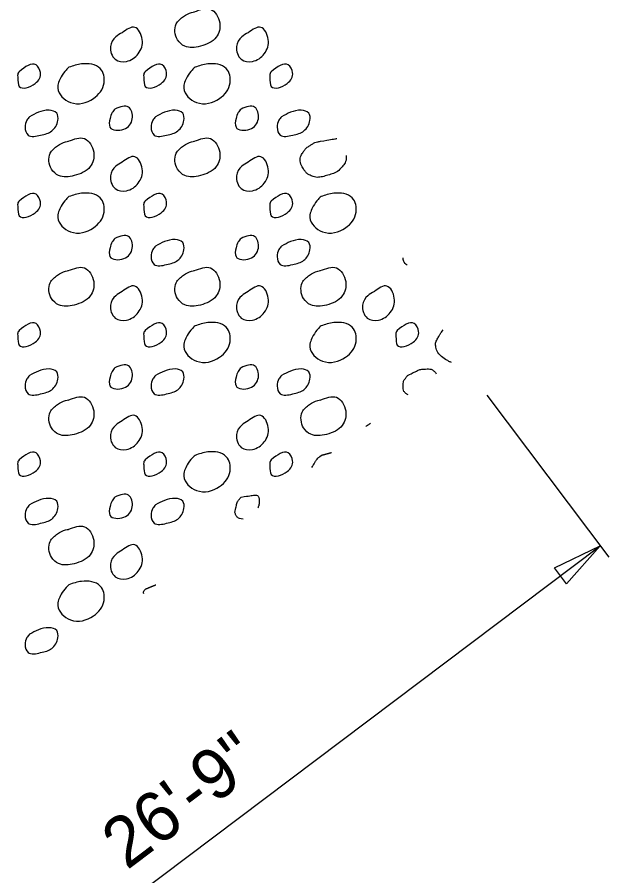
# Model space of a CAD drawing. Extents: x 0 to 1055, y 0 to 220.
# Drawn here: x 232.34 to 248.94, y 118.93 to 143.03 of the extents above; entities that cross this region are included whole.
import ezdxf

# ---------------------------------------------------------------- set-up
doc = ezdxf.new("R2010")
doc.units = 0
doc.layers.add('GE_P_Alignment_100_Distances', color=7, linetype='Continuous')
doc.layers.add('SC_Scratch1', color=7, linetype='Continuous')

msp = doc.modelspace()

# ---------------------------------------------------------------- linework, layer by layer
at = {"layer": 'GE_P_Alignment_100_Distances'}
for p, q in [((245.516, 132.423), (248.939, 127.874)), ((227.354, 112.125), (248.701, 128.19)), ((247.414, 127.572), (248.701, 128.19)), ((248.701, 128.19), (247.751, 127.125)), ((247.751, 127.125), (247.414, 127.572))]:
    msp.add_line(p, q, dxfattribs=at)
at = {"layer": 'SC_Scratch1'}
for points in [[(237.309, 143.177), (237.764, 143.252), (238.023, 142.872), (237.926, 142.466), (237.48, 142.213), (237.04, 142.216), (236.841, 142.394), (236.804, 142.839), (237.009, 143.052), (237.235, 143.161), (237.318, 143.178)], [(235.289, 142.594), (235.641, 142.745), (235.849, 142.407), (235.737, 142.002), (235.404, 141.789), (235.093, 141.848), (234.959, 142.207), (235.105, 142.475), (235.289, 142.594)], [(238.825, 142.594), (239.177, 142.745), (239.384, 142.407), (239.273, 142.002), (238.939, 141.789), (238.629, 141.848), (238.495, 142.207), (238.641, 142.475), (238.825, 142.594)], [(232.395, 141.499), (232.87, 141.692), (232.996, 141.473), (232.847, 141.171), (232.397, 141.087), (232.358, 141.327), (232.362, 141.447), (232.395, 141.499)], [(233.794, 141.625), (234.15, 141.718), (234.671, 141.587), (234.779, 141.184), (234.483, 140.749), (233.834, 140.638), (233.48, 141.037), (233.575, 141.355), (233.714, 141.547), (233.794, 141.625)], [(235.931, 141.499), (236.406, 141.692), (236.532, 141.473), (236.383, 141.171), (235.933, 141.087), (235.894, 141.327), (235.898, 141.447), (235.931, 141.499)], [(237.33, 141.625), (237.686, 141.718), (238.207, 141.587), (238.314, 141.184), (238.019, 140.749), (237.37, 140.638), (237.016, 141.037), (237.111, 141.355), (237.249, 141.547), (237.33, 141.625)], [(239.467, 141.499), (239.942, 141.692), (240.068, 141.473), (239.919, 141.171), (239.469, 141.087), (239.429, 141.327), (239.434, 141.447), (239.467, 141.499)], [(235.085, 140.452), (235.467, 140.508), (235.571, 140.179), (235.331, 139.885), (234.944, 139.942), (234.947, 140.188), (235.005, 140.351), (235.085, 140.452)], [(238.621, 140.452), (239.003, 140.508), (239.107, 140.179), (238.867, 139.885), (238.48, 139.942), (238.483, 140.188), (238.541, 140.351), (238.621, 140.452)], [(232.687, 140.235), (232.937, 140.36), (233.238, 140.418), (233.449, 140.337), (233.483, 140.134), (233.312, 139.837), (232.999, 139.717), (232.647, 139.723), (232.561, 139.939), (232.613, 140.139), (232.687, 140.235)], [(236.223, 140.235), (236.473, 140.36), (236.774, 140.418), (236.984, 140.337), (237.019, 140.134), (236.848, 139.837), (236.534, 139.717), (236.183, 139.723), (236.097, 139.939), (236.149, 140.139), (236.223, 140.235)], [(239.759, 140.235), (240.009, 140.36), (240.309, 140.418), (240.52, 140.337), (240.554, 140.134), (240.384, 139.837), (240.07, 139.717), (239.719, 139.723), (239.633, 139.939), (239.684, 140.139), (239.759, 140.235)], [(233.774, 139.546), (234.228, 139.622), (234.487, 139.242), (234.39, 138.835), (233.944, 138.583), (233.504, 138.585), (233.305, 138.764), (233.269, 139.209), (233.474, 139.422), (233.699, 139.53), (233.782, 139.548)], [(237.309, 139.546), (237.764, 139.622), (238.023, 139.242), (237.926, 138.835), (237.48, 138.583), (237.04, 138.585), (236.841, 138.764), (236.804, 139.209), (237.009, 139.422), (237.235, 139.53), (237.318, 139.548)], [(235.289, 138.964), (235.641, 139.114), (235.849, 138.776), (235.737, 138.371), (235.404, 138.159), (235.093, 138.218), (234.959, 138.577), (235.105, 138.844), (235.289, 138.964)], [(238.825, 138.964), (239.177, 139.114), (239.384, 138.776), (239.273, 138.371), (238.939, 138.159), (238.629, 138.218), (238.495, 138.577), (238.641, 138.844), (238.825, 138.964)], [(232.395, 137.869), (232.87, 138.061), (232.996, 137.843), (232.847, 137.54), (232.397, 137.456), (232.358, 137.696), (232.362, 137.817), (232.395, 137.869)], [(233.794, 137.994), (234.15, 138.088), (234.671, 137.956), (234.779, 137.554), (234.483, 137.119), (233.834, 137.008), (233.48, 137.406), (233.575, 137.724), (233.714, 137.917), (233.794, 137.994)], [(235.931, 137.869), (236.406, 138.061), (236.532, 137.843), (236.383, 137.54), (235.933, 137.456), (235.894, 137.696), (235.898, 137.817), (235.931, 137.869)], [(239.467, 137.869), (239.942, 138.061), (240.068, 137.843), (239.919, 137.54), (239.469, 137.456), (239.429, 137.696), (239.434, 137.817), (239.467, 137.869)], [(240.866, 137.994), (241.222, 138.088), (241.743, 137.956), (241.85, 137.554), (241.554, 137.119), (240.906, 137.008), (240.552, 137.406), (240.647, 137.724), (240.785, 137.917), (240.866, 137.994)], [(235.085, 136.821), (235.467, 136.877), (235.571, 136.549), (235.331, 136.255), (234.944, 136.311), (234.947, 136.557), (235.005, 136.721), (235.085, 136.821)], [(238.621, 136.821), (239.003, 136.877), (239.107, 136.549), (238.867, 136.255), (238.48, 136.311), (238.483, 136.557), (238.541, 136.721), (238.621, 136.821)], [(236.223, 136.605), (236.473, 136.73), (236.774, 136.787), (236.984, 136.706), (237.019, 136.503), (236.848, 136.206), (236.534, 136.086), (236.183, 136.092), (236.097, 136.308), (236.149, 136.508), (236.223, 136.605)], [(239.759, 136.605), (240.009, 136.73), (240.309, 136.787), (240.52, 136.706), (240.554, 136.503), (240.384, 136.206), (240.07, 136.086), (239.719, 136.092), (239.633, 136.308), (239.684, 136.508), (239.759, 136.605)], [(233.774, 135.916), (234.228, 135.991), (234.487, 135.611), (234.39, 135.205), (233.944, 134.952), (233.504, 134.955), (233.305, 135.133), (233.269, 135.578), (233.474, 135.791), (233.699, 135.9), (233.782, 135.917)], [(237.309, 135.916), (237.764, 135.991), (238.023, 135.611), (237.926, 135.205), (237.48, 134.952), (237.04, 134.955), (236.841, 135.133), (236.804, 135.578), (237.009, 135.791), (237.235, 135.9), (237.318, 135.917)], [(240.845, 135.916), (241.299, 135.991), (241.559, 135.611), (241.462, 135.205), (241.016, 134.952), (240.576, 134.955), (240.377, 135.133), (240.34, 135.578), (240.545, 135.791), (240.771, 135.9), (240.854, 135.917)], [(235.289, 135.333), (235.641, 135.484), (235.849, 135.146), (235.737, 134.741), (235.404, 134.528), (235.093, 134.587), (234.959, 134.946), (235.105, 135.214), (235.289, 135.333)], [(238.825, 135.333), (239.177, 135.484), (239.384, 135.146), (239.273, 134.741), (238.939, 134.528), (238.629, 134.587), (238.495, 134.946), (238.641, 135.214), (238.825, 135.333)], [(242.361, 135.333), (242.713, 135.484), (242.92, 135.146), (242.809, 134.741), (242.475, 134.528), (242.164, 134.587), (242.031, 134.946), (242.177, 135.214), (242.361, 135.333)], [(232.395, 134.238), (232.87, 134.431), (232.996, 134.212), (232.847, 133.91), (232.397, 133.826), (232.358, 134.066), (232.362, 134.186), (232.395, 134.238)], [(235.931, 134.238), (236.406, 134.431), (236.532, 134.212), (236.383, 133.91), (235.933, 133.826), (235.894, 134.066), (235.898, 134.186), (235.931, 134.238)], [(237.33, 134.364), (237.686, 134.457), (238.207, 134.326), (238.314, 133.923), (238.019, 133.488), (237.37, 133.377), (237.016, 133.776), (237.111, 134.094), (237.249, 134.286), (237.33, 134.364)], [(240.866, 134.364), (241.222, 134.457), (241.743, 134.326), (241.85, 133.923), (241.554, 133.488), (240.906, 133.377), (240.552, 133.776), (240.647, 134.094), (240.785, 134.286), (240.866, 134.364)], [(243.003, 134.238), (243.478, 134.431), (243.604, 134.212), (243.454, 133.91), (243.004, 133.826), (242.965, 134.066), (242.969, 134.186), (243.003, 134.238)], [(235.085, 133.191), (235.467, 133.247), (235.571, 132.918), (235.331, 132.624), (234.944, 132.681), (234.947, 132.927), (235.005, 133.09), (235.085, 133.191)], [(238.621, 133.191), (239.003, 133.247), (239.107, 132.918), (238.867, 132.624), (238.48, 132.681), (238.483, 132.927), (238.541, 133.09), (238.621, 133.191)], [(232.687, 132.974), (232.937, 133.099), (233.238, 133.157), (233.449, 133.076), (233.483, 132.873), (233.312, 132.576), (232.999, 132.456), (232.647, 132.462), (232.561, 132.678), (232.613, 132.878), (232.687, 132.974)], [(236.223, 132.974), (236.473, 133.099), (236.774, 133.157), (236.984, 133.076), (237.019, 132.873), (236.848, 132.576), (236.534, 132.456), (236.183, 132.462), (236.097, 132.678), (236.149, 132.878), (236.223, 132.974)], [(239.759, 132.974), (240.009, 133.099), (240.309, 133.157), (240.52, 133.076), (240.554, 132.873), (240.384, 132.576), (240.07, 132.456), (239.719, 132.462), (239.633, 132.678), (239.684, 132.878), (239.759, 132.974)], [(233.774, 132.285), (234.228, 132.361), (234.487, 131.981), (234.39, 131.574), (233.944, 131.322), (233.504, 131.324), (233.305, 131.503), (233.269, 131.948), (233.474, 132.161), (233.699, 132.269), (233.782, 132.287)], [(240.845, 132.285), (241.299, 132.361), (241.559, 131.981), (241.462, 131.574), (241.016, 131.322), (240.576, 131.324), (240.377, 131.503), (240.34, 131.948), (240.545, 132.161), (240.771, 132.269), (240.854, 132.287)], [(235.289, 131.703), (235.641, 131.853), (235.849, 131.515), (235.737, 131.11), (235.404, 130.898), (235.093, 130.957), (234.959, 131.316), (235.105, 131.583), (235.289, 131.703)], [(238.825, 131.703), (239.177, 131.853), (239.384, 131.515), (239.273, 131.11), (238.939, 130.898), (238.629, 130.957), (238.495, 131.316), (238.641, 131.583), (238.825, 131.703)], [(232.395, 130.608), (232.87, 130.8), (232.996, 130.582), (232.847, 130.279), (232.397, 130.195), (232.358, 130.435), (232.362, 130.556), (232.395, 130.608)], [(235.931, 130.608), (236.406, 130.8), (236.532, 130.582), (236.383, 130.279), (235.933, 130.195), (235.894, 130.435), (235.898, 130.556), (235.931, 130.608)], [(239.467, 130.608), (239.942, 130.8), (240.068, 130.582), (239.919, 130.279), (239.469, 130.195), (239.429, 130.435), (239.434, 130.556), (239.467, 130.608)], [(237.33, 130.733), (237.686, 130.827), (238.207, 130.695), (238.314, 130.293), (238.019, 129.858), (237.37, 129.747), (237.016, 130.145), (237.111, 130.463), (237.249, 130.656), (237.33, 130.733)], [(235.085, 129.561), (235.467, 129.616), (235.571, 129.288), (235.331, 128.994), (234.944, 129.051), (234.947, 129.296), (235.005, 129.46), (235.085, 129.561)], [(232.687, 129.344), (232.937, 129.469), (233.238, 129.526), (233.449, 129.446), (233.483, 129.242), (233.312, 128.946), (232.999, 128.826), (232.647, 128.831), (232.561, 129.047), (232.613, 129.247), (232.687, 129.344)], [(236.223, 129.344), (236.473, 129.469), (236.774, 129.526), (236.984, 129.446), (237.019, 129.242), (236.848, 128.946), (236.534, 128.826), (236.183, 128.831), (236.097, 129.047), (236.149, 129.247), (236.223, 129.344)], [(233.774, 128.655), (234.228, 128.731), (234.487, 128.351), (234.39, 127.944), (233.944, 127.691), (233.504, 127.694), (233.305, 127.872), (233.269, 128.317), (233.474, 128.531), (233.699, 128.639), (233.782, 128.656)], [(235.289, 128.072), (235.641, 128.223), (235.849, 127.885), (235.737, 127.48), (235.404, 127.267), (235.093, 127.326), (234.959, 127.686), (235.105, 127.953), (235.289, 128.072)], [(233.794, 127.103), (234.15, 127.196), (234.671, 127.065), (234.779, 126.662), (234.483, 126.227), (233.834, 126.116), (233.48, 126.515), (233.575, 126.833), (233.714, 127.026), (233.794, 127.103)], [(232.687, 125.713), (232.937, 125.838), (233.238, 125.896), (233.449, 125.815), (233.483, 125.612), (233.312, 125.315), (232.999, 125.195), (232.647, 125.201), (232.561, 125.417), (232.613, 125.617), (232.687, 125.713)]]:
    msp.add_spline(points, degree=3, dxfattribs=at)
for points, degree in [([(241.573, 139.149), (241.578, 139.042), (241.546, 138.928), (241.462, 138.835), (241.329, 138.688), (241.181, 138.631), (241.016, 138.583), (240.875, 138.541), (240.717, 138.526), (240.576, 138.585), (240.491, 138.621), (240.429, 138.683), (240.377, 138.764), (240.29, 138.898), (240.265, 139.082), (240.34, 139.209), (240.39, 139.292), (240.458, 139.367), (240.545, 139.422), (240.619, 139.469), (240.689, 139.513), (240.771, 139.53), (240.799, 139.536), (240.826, 139.542), (240.854, 139.548)], 3), ([(240.845, 139.546), (240.997, 139.572), (241.148, 139.601), (241.299, 139.622), (241.303, 139.622), (241.306, 139.623), (241.31, 139.623)], 3), ([(243.281, 136.072), (243.272, 136.078), (243.263, 136.085), (243.254, 136.092), (243.193, 136.147), (243.173, 136.21), (243.169, 136.273)], 3), ([(244.522, 133.341), (244.495, 133.35), (244.468, 133.362), (244.442, 133.377), (244.284, 133.471), (244.118, 133.611), (244.088, 133.776), (244.069, 133.879), (244.122, 133.998), (244.183, 134.094), (244.218, 134.149), (244.249, 134.205), (244.29, 134.253)], 3), ([(243.294, 132.974), (243.378, 133.016), (243.461, 133.058), (243.544, 133.099), (243.636, 133.145), (243.745, 133.154), (243.845, 133.157), (243.919, 133.159), (243.99, 133.142), (244.056, 133.076), (244.074, 133.058), (244.086, 133.038), (244.093, 133.018)], 3), ([(243.308, 132.427), (243.29, 132.435), (243.272, 132.446), (243.254, 132.462), (243.182, 132.527), (243.167, 132.603), (243.169, 132.678), (243.17, 132.744), (243.178, 132.822), (243.22, 132.878), (243.245, 132.91), (243.27, 132.942), (243.294, 132.974)], 3), ([(242.127, 131.538), (242.142, 131.555), (242.158, 131.571), (242.177, 131.583), (242.203, 131.601), (242.229, 131.617), (242.254, 131.634)], 3), ([(240.607, 130.395), (240.62, 130.418), (240.633, 130.442), (240.647, 130.463), (240.69, 130.532), (240.728, 130.601), (240.785, 130.656), (240.812, 130.682), (240.839, 130.708), (240.866, 130.733)], 3), ([(240.866, 130.733), (240.964, 130.76), (241.062, 130.785), (241.161, 130.811)], 2), ([(238.68, 128.944), (238.595, 128.948), (238.514, 128.983), (238.48, 129.051), (238.442, 129.128), (238.461, 129.218), (238.483, 129.296), (238.498, 129.351), (238.505, 129.414), (238.541, 129.46), (238.568, 129.493), (238.594, 129.527), (238.621, 129.561)], 3), ([(238.621, 129.561), (238.748, 129.579), (238.876, 129.599), (239.003, 129.616), (239.116, 129.632), (239.143, 129.386), (239.107, 129.288), (239.103, 129.277), (239.098, 129.266), (239.093, 129.255)], 3), ([(235.931, 126.977), (236.03, 127.017), (236.13, 127.059), (236.229, 127.099)], 2), ([(235.89, 126.844), (235.886, 126.873), (235.884, 126.901), (235.898, 126.926), (235.908, 126.944), (235.92, 126.96), (235.931, 126.977)], 3)]:
    msp.add_open_spline(points, degree=degree, dxfattribs=at)

# ---------------------------------------------------------------- texts
at = {"layer": 'GE_P_Alignment_100_Distances'}
msp.add_text('26\'-9"', height=1.41, rotation=36.963, dxfattribs=at).set_placement((235.419, 119.077))

doc.saveas('drawing.dxf')
